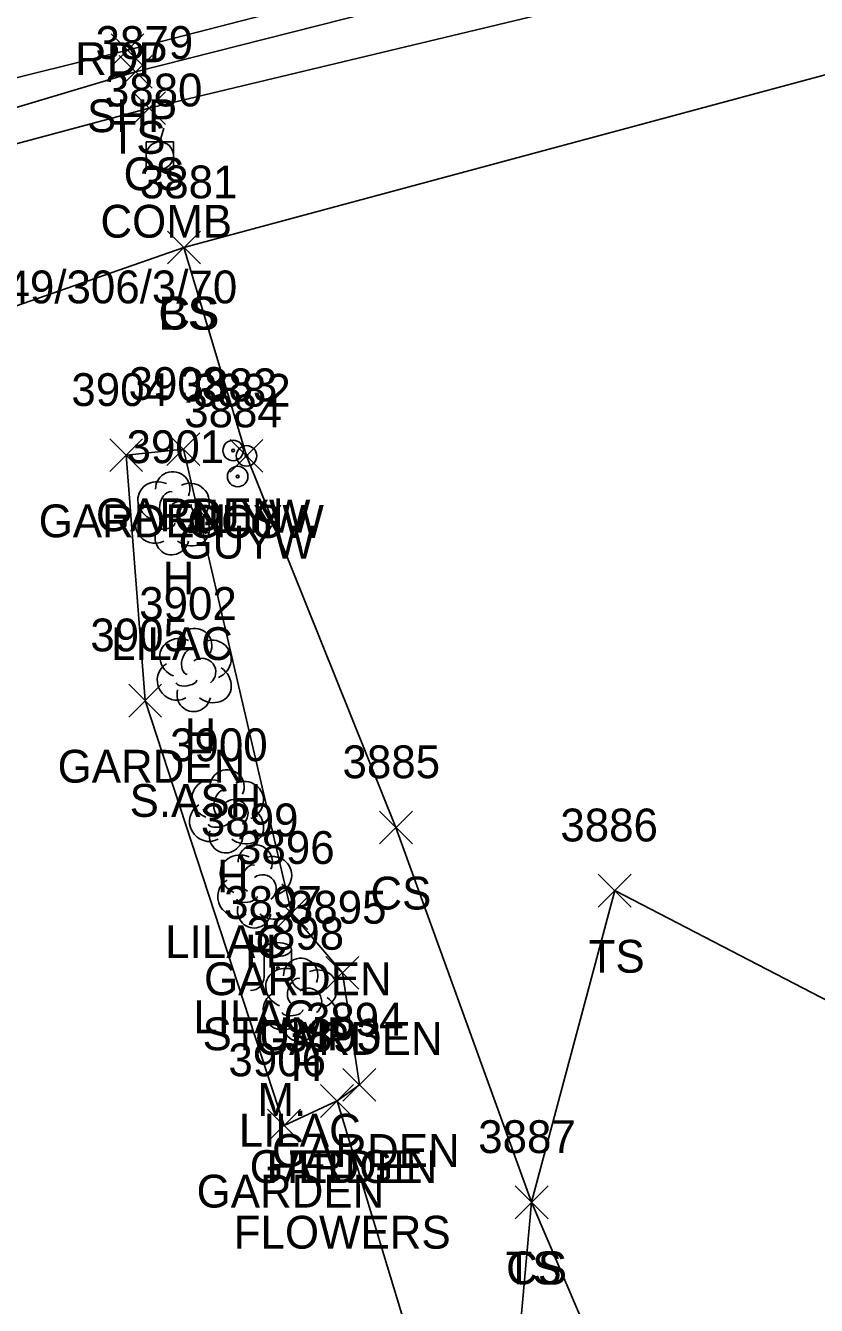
# Model space of a CAD drawing. Extents: x 1520648 to 1523413, y 732854 to 735518.
# Drawn here: x 1521146.6 to 1521194.8, y 733427.9 to 733505.9 of the extents above; entities that cross this region are included whole.
import ezdxf

# ---------------------------------------------------------------- set-up
doc = ezdxf.new("R2010")
doc.units = 0
for name, color, linetype in [('L_A', 7, 'Continuous'), ('L_C', 7, 'Continuous'), ('L_I', 7, 'Continuous'), ('L_TIC', 7, 'Continuous'), ('LAHR', 7, 'Continuous'), ('LAPB', 7, 'Continuous'), ('LELB', 7, 'Continuous'), ('LTD', 7, 'Continuous'), ('LTS', 7, 'Continuous'), ('P_A', 7, 'Continuous'), ('P_TIC', 7, 'Continuous'), ('PSP', 7, 'Continuous'), ('U_A', 7, 'Continuous'), ('U_C', 7, 'Continuous'), ('U_I', 7, 'Continuous'), ('UP', 7, 'Continuous'), ('UPGW', 7, 'Continuous')]:
    doc.layers.add(name, color=color, linetype=linetype)

msp = doc.modelspace()

# ---------------------------------------------------------------- linework, layer by layer
at = {"layer": 'L_TIC'}
for points in [[(1521152.312, 733502.047), (1521154.312, 733504.047)], [(1521154.312, 733502.047), (1521152.312, 733504.047)], [(1521153.138, 733499.827), (1521155.138, 733501.827)], [(1521155.138, 733499.827), (1521153.138, 733501.827)], [(1521155.262, 733491.333), (1521157.262, 733493.333)], [(1521157.262, 733491.333), (1521155.262, 733493.333)], [(1521155.262, 733491.333), (1521157.262, 733493.333)], [(1521157.262, 733491.333), (1521155.262, 733493.333)], [(1521155.223, 733479.045), (1521157.223, 733481.045)], [(1521157.223, 733479.045), (1521155.223, 733481.045)], [(1521151.735, 733478.677), (1521153.735, 733480.677)], [(1521153.735, 733478.677), (1521151.735, 733480.677)], [(1521159.076, 733478.636), (1521161.076, 733480.636)], [(1521161.076, 733478.636), (1521159.076, 733480.636)], [(1521152.891, 733463.724), (1521154.891, 733465.724)], [(1521154.891, 733463.724), (1521152.891, 733465.724)], [(1521168.187, 733455.994), (1521170.187, 733457.994)], [(1521170.187, 733455.994), (1521168.187, 733457.994)], [(1521181.522, 733452.142), (1521183.522, 733454.142)], [(1521183.522, 733452.142), (1521181.522, 733454.142)], [(1521161.812, 733450.77), (1521163.812, 733452.77)], [(1521163.812, 733450.77), (1521161.812, 733452.77)], [(1521164.918, 733447.132), (1521166.918, 733449.132)], [(1521166.918, 733447.132), (1521164.918, 733449.132)], [(1521165.956, 733440.306), (1521167.956, 733442.306)], [(1521167.956, 733440.306), (1521165.956, 733442.306)], [(1521164.595, 733439.326), (1521166.595, 733441.326)], [(1521166.595, 733439.326), (1521164.595, 733441.326)], [(1521164.595, 733439.326), (1521166.595, 733441.326)], [(1521166.595, 733439.326), (1521164.595, 733441.326)], [(1521164.595, 733439.326), (1521166.595, 733441.326)], [(1521166.595, 733439.326), (1521164.595, 733441.326)], [(1521161.363, 733437.829), (1521163.363, 733439.829)], [(1521163.363, 733437.829), (1521161.363, 733439.829)], [(1521161.363, 733437.829), (1521163.363, 733439.829)], [(1521163.363, 733437.829), (1521161.363, 733439.829)], [(1521176.459, 733433.149), (1521178.459, 733435.149)], [(1521178.459, 733433.149), (1521176.459, 733435.149)], [(1521176.459, 733433.149), (1521178.459, 733435.149)], [(1521178.459, 733433.149), (1521176.459, 733435.149)]]:
    msp.add_lwpolyline(points, dxfattribs=at)
at = {"layer": 'LAHR'}
msp.add_lwpolyline([(1521171.906, 733419.556), (1521165.595, 733440.326)], dxfattribs=at)
at = {"layer": 'LAPB'}
for points in [[(1521165.595, 733440.326), (1521166.956, 733441.306), (1521165.918, 733448.132), (1521162.812, 733451.77), (1521156.223, 733480.045), (1521152.735, 733479.677), (1521153.891, 733464.724), (1521162.363, 733438.829)], [(1521165.595, 733440.326), (1521162.363, 733438.829)]]:
    msp.add_lwpolyline(points, dxfattribs=at)
at = {"layer": 'LELB'}
for points in [[(1521446.759, 733575.985), (1521399.637, 733563.42), (1521368.024, 733555.683), (1521310.834, 733539.577), (1521307.985, 733540.201), (1521245.462, 733523.723), (1521206.197, 733513.3), (1521154.138, 733500.827), (1521129.341, 733494.185)], [(1521367.255, 733558.107), (1521307.77, 733542.6), (1521244.979, 733526.432), (1521205.634, 733516.31), (1521153.312, 733503.047), (1521110.069, 733490.115), (1521103.608, 733488.919)], [(1521370.394, 733548.57), (1521314.231, 733532.31), (1521247.211, 733516.912), (1521208.343, 733506.348), (1521156.262, 733492.333), (1521131.753, 733483.81)], [(1521156.262, 733492.333), (1521160.076, 733479.636), (1521169.187, 733456.994), (1521177.459, 733434.149), (1521186.103, 733413.911), (1521183.967, 733404.146)], [(1521252.104, 733415.19), (1521228.37, 733429.385), (1521182.522, 733453.142), (1521177.459, 733434.149), (1521175.05, 733407.453), (1521132.836, 733393.748), (1521088.037, 733381.942)]]:
    msp.add_lwpolyline(points, dxfattribs=at)
at = {"layer": 'LTD'}
for p, q in [((1521155.533, 733476.196), (1521155.533, 733476.196)), ((1521155.533, 733476.196), (1521155.533, 733476.196)), ((1521156.871, 733466.64), (1521156.871, 733466.64)), ((1521156.871, 733466.64), (1521156.871, 733466.64)), ((1521158.839, 733458.031), (1521158.839, 733458.031)), ((1521158.839, 733458.031), (1521158.839, 733458.031)), ((1521160.56, 733453.453), (1521160.56, 733453.453)), ((1521160.56, 733453.453), (1521160.56, 733453.453)), ((1521163.332, 733446.542), (1521163.332, 733446.542)), ((1521163.332, 733446.542), (1521163.332, 733446.542))]:
    msp.add_line(p, q, dxfattribs=at)
for centre in [(1521155.58, 733477.63), (1521156.917, 733468.074), (1521158.886, 733459.465), (1521160.607, 733454.887), (1521163.379, 733447.976)]:
    msp.add_arc(centre, 1.047, 335.52715, 180.95627, dxfattribs=at)
for centre, major_axis, ratio, start_param, end_param in [((1521154.742, 733476.862), (1.21, -0.512), 0.895232, 1.570796, 4.712389), ((1521156.575, 733476.779), (-1.141, -0.483), 0.949671, 1.570796, 4.712389), ((1521155.325, 733476.654), (-0.208, -0.792), 0.645439, 3.141593, 6.283185), ((1521156.033, 733476.029), (-0.5, 0.667), 0.989748, 3.141593, 6.283185), ((1521154.45, 733475.487), (0.584, -1.042), 0.959034, 3.141593, 6.283185), ((1521156.534, 733475.363), (-1.09, 0.792), 0.841452, 1.570796, 4.712389), ((1521155.075, 733475.446), (-0.625, -0.083), 0.423636, 0, 3.141593), ((1521155.534, 733474.696), (0.265, 1.061), 0.942809, 1.570796, 4.712389), ((1521156.079, 733467.307), (1.21, -0.512), 0.895232, 1.570796, 4.712389), ((1521157.912, 733467.224), (-1.141, -0.483), 0.949671, 1.570796, 4.712389), ((1521156.662, 733467.099), (-0.208, -0.792), 0.645439, 3.141593, 6.283185), ((1521155.788, 733465.932), (0.584, -1.042), 0.959034, 3.141593, 6.283185), ((1521157.371, 733466.474), (-0.5, 0.667), 0.989748, 3.141593, 6.283185), ((1521157.871, 733465.807), (-1.09, 0.792), 0.841452, 1.570796, 4.712389), ((1521156.413, 733465.89), (-0.625, -0.083), 0.423636, 0, 3.141593), ((1521156.871, 733465.14), (0.265, 1.061), 0.942809, 1.570796, 4.712389), ((1521158.047, 733458.698), (1.21, -0.512), 0.895232, 1.570796, 4.712389), ((1521159.88, 733458.615), (-1.141, -0.483), 0.949671, 1.570796, 4.712389), ((1521158.631, 733458.49), (-0.208, -0.792), 0.645439, 3.141593, 6.283185), ((1521157.756, 733457.323), (0.584, -1.042), 0.959034, 3.141593, 6.283185), ((1521159.339, 733457.865), (-0.5, 0.667), 0.989748, 3.141593, 6.283185), ((1521159.839, 733457.198), (-1.09, 0.792), 0.841452, 1.570796, 4.712389), ((1521158.381, 733457.281), (-0.625, -0.083), 0.423636, 0, 3.141593), ((1521158.839, 733456.531), (0.265, 1.061), 0.942809, 1.570796, 4.712389), ((1521159.768, 733454.119), (1.21, -0.512), 0.895232, 1.570796, 4.712389), ((1521161.601, 733454.036), (-1.141, -0.483), 0.949671, 1.570796, 4.712389), ((1521160.351, 733453.911), (-0.208, -0.792), 0.645439, 3.141593, 6.283185), ((1521161.06, 733453.286), (-0.5, 0.667), 0.989748, 3.141593, 6.283185), ((1521159.477, 733452.744), (0.584, -1.042), 0.959034, 3.141593, 6.283185), ((1521161.56, 733452.62), (-1.09, 0.792), 0.841452, 1.570796, 4.712389), ((1521160.102, 733452.703), (-0.625, -0.083), 0.423636, 0, 3.141593), ((1521160.56, 733451.953), (0.265, 1.061), 0.942809, 1.570796, 4.712389), ((1521162.54, 733447.209), (1.21, -0.512), 0.895232, 1.570796, 4.712389), ((1521164.373, 733447.126), (-1.141, -0.483), 0.949671, 1.570796, 4.712389), ((1521163.123, 733447), (-0.208, -0.792), 0.645439, 3.141593, 6.283185), ((1521163.832, 733446.375), (-0.5, 0.667), 0.989748, 3.141593, 6.283185), ((1521162.249, 733445.833), (0.584, -1.042), 0.959034, 3.141593, 6.283185), ((1521164.332, 733445.709), (-1.09, 0.792), 0.841452, 1.570796, 4.712389), ((1521162.874, 733445.792), (-0.625, -0.083), 0.423636, 0, 3.141593), ((1521163.332, 733445.042), (0.265, 1.061), 0.942809, 1.570796, 4.712389)]:
    msp.add_ellipse(centre, major_axis=major_axis, ratio=ratio, start_param=start_param, end_param=end_param, dxfattribs=at)
at = {"layer": 'LTS'}
for p, q in [((1521161.142, 733449.557), (1521161.142, 733447.89)), ((1521162.809, 733449.39), (1521162.809, 733449.557)), ((1521162.809, 733449.557), (1521162.809, 733447.89)), ((1521161.976, 733448.415), (1521161.976, 733448.415)), ((1521161.976, 733448.415), (1521161.976, 733448.415)), ((1521161.976, 733448.39), (1521161.976, 733448.39))]:
    msp.add_line(p, q, dxfattribs=at)
msp.add_circle((1521161.976, 733448.415), 0.0833, dxfattribs=at)
for centre, start, end in [((1521160.309, 733447.89), 270, 360), ((1521163.642, 733447.89), 180, 270)]:
    msp.add_arc(centre, 0.833, start, end, dxfattribs=at)
msp.add_ellipse((1521161.976, 733449.557), major_axis=(-0.833, 0), ratio=0.5, dxfattribs=at)
at = {"layer": 'P_TIC'}
for points in [[(1521151.818, 733503.366), (1521153.818, 733505.366)], [(1521153.818, 733503.366), (1521151.818, 733505.366)]]:
    msp.add_lwpolyline(points, dxfattribs=at)
at = {"layer": 'PSP'}
msp.add_lwpolyline([(1521366.854, 733559.74), (1521307.162, 733544.247), (1521244.305, 733528.244), (1521204.944, 733517.791), (1521152.818, 733504.366), (1521106.573, 733492.891), (1521080.1, 733485.883), (1521063.464, 733481.981), (1521018.865, 733470.553), (1520976.521, 733459.1), (1520931.664, 733447.126), (1520886.569, 733435.142), (1520877.932, 733432.708), (1520850.753, 733426.015), (1520817.824, 733417.126), (1520781.504, 733407.406), (1520747.692, 733397.942), (1520743.137, 733395.112), (1520720.817, 733389.467), (1520716.87, 733390.018), (1520705.401, 733386.95), (1520679.313, 733380.336)], dxfattribs=at)
at = {"layer": 'UP'}
for p, q in [((1521155.034, 733499.601), (1521154.784, 733498.768)), ((1521153.95, 733497.101), (1521153.95, 733498.768)), ((1521153.95, 733498.768), (1521155.617, 733498.768)), ((1521155.617, 733498.768), (1521155.617, 733497.101)), ((1521154.784, 733497.935), (1521154.784, 733497.935)), ((1521155.617, 733497.101), (1521153.95, 733497.101)), ((1521154.534, 733496.268), (1521154.784, 733497.101))]:
    msp.add_line(p, q, dxfattribs=at)
msp.add_circle((1521154.784, 733497.935), 0.833, dxfattribs=at)
at = {"layer": 'UPGW'}
for centre, radius in [((1521159.258, 733479.968), 0.625), ((1521159.258, 733479.968), 0.0833), ((1521160.076, 733479.636), 0.625), ((1521160.076, 733479.636), 0.0833), ((1521159.535, 733478.379), 0.625), ((1521159.535, 733478.379), 0.0833)]:
    msp.add_circle(centre, radius, dxfattribs=at)

# ---------------------------------------------------------------- texts
at = {"layer": 'L_A'}
for s, p in [('TS', (1521151.721, 733498.047)), ('CS', (1521152.579, 733495.827)), ('CS', (1521154.703, 733487.333)), ('BS', (1521154.703, 733487.333)), ('GARDEN', (1521150.893, 733475.045)), ('GARDEN', (1521147.404, 733474.677)), ('CS', (1521158.517, 733474.636)), ('H', (1521154.966, 733471.196)), ('H', (1521156.304, 733461.64)), ('GARDEN', (1521148.56, 733459.724)), ('H', (1521158.272, 733453.031)), ('CS', (1521167.628, 733451.994)), ('H', (1521159.993, 733448.453)), ('TS', (1521180.932, 733448.142)), ('GARDEN', (1521157.482, 733446.77)), ('STUMP', (1521157.397, 733443.417)), ('GARDEN', (1521160.587, 733443.132)), ('H', (1521162.765, 733441.542)), ('GARDEN', (1521161.626, 733436.306)), ('GARDEN', (1521160.264, 733435.326)), ('GARDEN', (1521160.264, 733435.326)), ('HEDGE', (1521161.296, 733435.326)), ('GARDEN', (1521157.033, 733433.829)), ('GARDEN', (1521157.033, 733433.829)), ('TS', (1521175.868, 733429.149)), ('CS', (1521175.9, 733429.149))]:
    msp.add_text(s, height=2, dxfattribs=at).set_placement(p)
at = {"layer": 'L_C'}
for s, p in [('LILAC', (1521151.809, 733467.196)), ('S.ASH', (1521152.949, 733457.64)), ('LILAC', (1521155.115, 733449.031)), ('LILAC', (1521156.835, 733444.453)), ('M.', (1521160.743, 733439.417)), ('LILAC', (1521159.607, 733437.542)), ('FLOWERS', (1521159.296, 733431.326))]:
    msp.add_text(s, height=2, dxfattribs=at).set_placement(p)
at = {"layer": 'L_I'}
for s, p in [('3879', (1521150.871, 733503.827)), ('3881', (1521153.569, 733495.333)), ('3881', (1521153.569, 733495.333)), ('3904', (1521149.396, 733482.677)), ('3903', (1521152.885, 733483.045)), ('3882', (1521156.816, 733482.636)), ('3901', (1521152.762, 733479.196)), ('3902', (1521153.532, 733469.64)), ('3905', (1521150.552, 733467.724)), ('3900', (1521155.414, 733461.031)), ('3885', (1521165.927, 733459.994)), ('3899', (1521157.292, 733456.453)), ('3886', (1521179.207, 733456.142)), ('3896', (1521159.497, 733454.77)), ('3897', (1521158.711, 733451.417)), ('3895', (1521162.658, 733451.132)), ('3898', (1521160.072, 733449.542)), ('3894', (1521163.697, 733444.306)), ('3893', (1521162.335, 733443.326)), ('3893', (1521162.335, 733443.326)), ('3893', (1521162.335, 733443.326)), ('3906', (1521158.97, 733441.829)), ('3906', (1521158.97, 733441.829)), ('3887', (1521174.199, 733437.149)), ('3887', (1521174.199, 733437.149))]:
    msp.add_text(s, height=2, dxfattribs=at).set_placement(p)
at = {"layer": 'P_A'}
for s, p in [('RDP', (1521149.629, 733502.848)), ('SHP', (1521150.353, 733499.366))]:
    msp.add_text(s, height=2, dxfattribs=at).set_placement(p)
at = {"layer": 'U_A'}
for s, p in [('COMB', (1521151.169, 733492.935)), ('GUYW', (1521155.652, 733474.968)), ('GUYW', (1521156.47, 733474.636)), ('GUYW', (1521155.929, 733473.379))]:
    msp.add_text(s, height=2, dxfattribs=at).set_placement(p)
at = {"layer": 'U_C'}
msp.add_text('349/306/3/70', height=2, dxfattribs=at).set_placement((1521143.894, 733488.935))
at = {"layer": 'U_I'}
for s, p in [('3880', (1521151.437, 733500.935)), ('3883', (1521155.998, 733482.968)), ('3882', (1521156.816, 733482.636)), ('3884', (1521156.275, 733481.379))]:
    msp.add_text(s, height=2, dxfattribs=at).set_placement(p)

doc.saveas('drawing.dxf')
